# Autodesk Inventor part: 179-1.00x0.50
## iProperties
Created: 2007-06
Part Number: 179-1.00x0.50
Document SubType Name: Modeling
Designer: btaylor
Density: 1 g/cm^3
Author: btaylor
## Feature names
1. Extrusion1
2. Extrusion3
3. Extrusion9
4. Fillet3
5. Fillet6
6. Extrusion10
7. Extrusion7
8. Extrusion11
9. Chamfer3
10. Chamfer4
11. Fillet7
12. Fillet8
13. Revolution2
